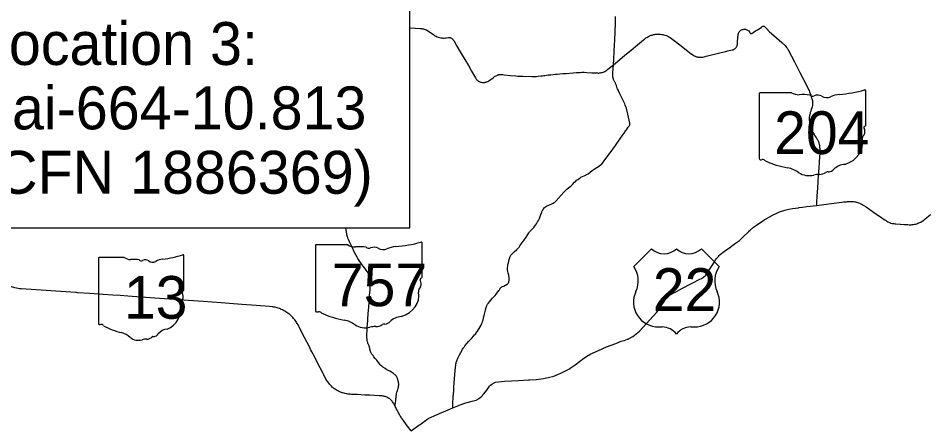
# Model space of a CAD drawing. Extents: x 1761803 to 2441803, y 509895 to 949895.
# Drawn here: x 1999264 to 2058370, y 753523 to 780187 of the extents above; entities that cross this region are included whole.
import ezdxf

# ---------------------------------------------------------------- set-up
doc = ezdxf.new("R2010")
doc.units = 0
for name, color, linetype in [('Default', 7, 'Continuous'), ('GM_X_County_Road_Text', 7, 'Continuous'), ('GM_X_Minor_Lake', 7, 'Continuous'), ('GM_X_Minor_River_Text', 7, 'Continuous'), ('GM_X_State_Location', 7, 'Continuous'), ('GM_X_Township_Road', 7, 'Continuous')]:
    doc.layers.add(name, color=color, linetype=linetype)

msp = doc.modelspace()

# ---------------------------------------------------------------- linework, layer by layer
at = {"layer": 'Default'}
msp.add_lwpolyline([(1995413, 766506), (2024789, 766506), (2024789, 781340), (1995413, 781340)], close=True, dxfattribs=at)
at = {"layer": 'GM_X_County_Road_Text'}
for p, q in [((2040554, 765146), (2039394, 763986)), ((2044963, 763986), (2043803, 765146)), ((2041018, 760041), (2041250, 760041)), ((2043107, 760041), (2043339, 760041))]:
    msp.add_line(p, q, dxfattribs=at)
for centre, radius, start, end in [((2041366, 765975), 1160, 225.573, 314.427), ((2042991, 765975), 1160, 225.573, 314.427), ((2038064, 763054), 1624, 334.54712, 35.00093), ((2046293, 763054), 1624, 144.99907, 205.45288), ((2041000, 761665), 1624, 154.83192, 270.63826), ((2043357, 761665), 1624, 269.36174, 25.16808), ((2041250, 758881), 1160, 36.8699, 90), ((2043107, 758881), 1160, 90, 143.1301)]:
    msp.add_arc(centre, radius, start, end, dxfattribs=at)
at = {"layer": 'GM_X_Minor_Lake'}
for points in [[(2038068, 777149), (2038085, 777516), (2038113, 777993), (2038138, 778487), (2038152, 778703), (2038183, 779333), (2038202, 779829), (2038213, 780293)], [(2045835, 778118), (2045864, 778126), (2045893, 778137), (2045932, 778154), (2045968, 778175), (2045999, 778199), (2046030, 778225), (2046063, 778262), (2046095, 778307), (2046116, 778353), (2046129, 778384), (2046138, 778421), (2046149, 778480), (2046157, 778584), (2046188, 778991), (2046194, 779050), (2046200, 779092), (2046207, 779130), (2046215, 779164), (2046225, 779197), (2046245, 779243), (2046267, 779283), (2046293, 779317), (2046320, 779348), (2046358, 779383), (2046381, 779401), (2046410, 779417), (2046453, 779438), (2046503, 779455), (2046559, 779465), (2046617, 779467), (2046671, 779461), (2046723, 779449), (2046772, 779431), (2046818, 779407), (2046857, 779380), (2046890, 779348), (2046929, 779300), (2046962, 779248), (2046986, 779212), (2046999, 779195), (2047013, 779184), (2047025, 779178), (2047041, 779173), (2047055, 779172), (2047068, 779175), (2047092, 779186), (2047188, 779249), (2047327, 779348), (2047457, 779433), (2047627, 779541), (2047718, 779600), (2047772, 779641), (2047798, 779659), (2047806, 779663), (2047816, 779667), (2047829, 779670), (2047842, 779671), (2047856, 779670), (2047869, 779668), (2047879, 779663), (2047888, 779658), (2047912, 779640), (2047957, 779603), (2048026, 779542), (2048071, 779482), (2048125, 779418)], [(2024789, 779552), (2024814, 779551), (2025158, 779531), (2025478, 779509), (2025571, 779500), (2025633, 779493), (2025678, 779486), (2025741, 779472), (2025801, 779453), (2025853, 779431), (2025908, 779402), (2026024, 779328), (2026227, 779185), (2026330, 779115), (2026377, 779081), (2026439, 779041), (2026512, 779000), (2026573, 778972), (2026645, 778944), (2026741, 778920), (2026814, 778903), (2026885, 778890), (2026948, 778882), (2026988, 778882), (2027045, 778885), (2027128, 778895), (2027185, 778902), (2027316, 778918), (2027339, 778920), (2027366, 778921), (2027393, 778920), (2027420, 778915), (2027445, 778906), (2027479, 778893), (2027508, 778877), (2027544, 778855), (2027572, 778831), (2027602, 778802), (2027622, 778779), (2027638, 778756), (2027657, 778722), (2027869, 778355), (2028081, 777996), (2028385, 777482), (2028616, 777087), (2028827, 776724), (2029079, 776288), (2029099, 776255), (2029125, 776219), (2029145, 776191), (2029161, 776172), (2029185, 776150), (2029215, 776124), (2029244, 776102), (2029279, 776079), (2029323, 776053), (2029365, 776033), (2029407, 776015), (2029455, 776003), (2029508, 775991), (2029555, 775985), (2029621, 775985), (2029672, 775992), (2029707, 775999), (2029743, 776007), (2029783, 776020), (2029826, 776037), (2029876, 776061), (2029938, 776097), (2030225, 776302), (2030317, 776368), (2030368, 776401), (2030416, 776428), (2030463, 776450), (2030502, 776466), (2030543, 776481), (2030580, 776492), (2030608, 776499), (2030641, 776504), (2030685, 776510), (2030746, 776512), (2030797, 776510), (2030849, 776506), (2030950, 776498), (2031368, 776452), (2031712, 776417), (2031833, 776405), (2031888, 776401), (2032002, 776395), (2032186, 776392), (2032744, 776387), (2033053, 776388), (2033173, 776395), (2033326, 776417)], [(2036084, 776653), (2036166, 776651), (2036338, 776646), (2036654, 776628), (2036891, 776613), (2037021, 776607), (2037071, 776604), (2037120, 776606), (2037170, 776610), (2037224, 776616), (2037281, 776629), (2037341, 776645), (2037409, 776668), (2037460, 776690), (2037510, 776715), (2037579, 776757), (2037638, 776800), (2037696, 776846), (2038068, 777149), (2038480, 777486), (2038820, 777769), (2039225, 778107), (2039631, 778442), (2040024, 778768), (2040090, 778820), (2040139, 778856), (2040191, 778894), (2040250, 778932), (2040306, 778964), (2040361, 778991), (2040429, 779023), (2040530, 779065), (2040594, 779085), (2040639, 779098), (2040689, 779110), (2040746, 779121), (2040800, 779130), (2040844, 779136), (2040902, 779140), (2040969, 779142), (2041047, 779141), (2041134, 779137), (2041214, 779128), (2041280, 779117), (2041359, 779099), (2041447, 779072), (2041522, 779047), (2041609, 779008), (2041682, 778969), (2041728, 778944), (2041770, 778916), (2042017, 778737), (2042396, 778441), (2042927, 778027), (2043166, 777846), (2043171, 777840), (2043241, 777787), (2043284, 777758), (2043326, 777732), (2043359, 777716), (2043398, 777698), (2043449, 777679), (2043490, 777666), (2043546, 777653), (2043596, 777644), (2043659, 777638), (2043717, 777635), (2043788, 777635), (2043849, 777640), (2043897, 777648), (2043979, 777667), (2044105, 777699), (2044372, 777769), (2044926, 777902), (2045376, 778007), (2045614, 778065), (2045732, 778093), (2045807, 778111), (2045835, 778118)], [(2048125, 779418), (2048136, 779404), (2048184, 779355), (2048253, 779292), (2048364, 779193), (2048703, 778894), (2049042, 778605), (2049103, 778550), (2049143, 778514), (2049182, 778477), (2049219, 778440), (2049262, 778395), (2049316, 778333), (2049357, 778280), (2049392, 778232), (2049424, 778184), (2049453, 778135), (2049489, 778073), (2049677, 777706), (2049873, 777325), (2050064, 776944), (2050225, 776635), (2050463, 776177), (2050671, 775777), (2050793, 775537), (2050827, 775460), (2050853, 775388), (2050928, 775155), (2050959, 775056), (2051016, 774888), (2051035, 774823), (2051045, 774776), (2051054, 774720), (2051055, 774652), (2051048, 774572), (2051035, 774479), (2051019, 774398), (2051005, 774334), (2050964, 774216), (2050927, 774113), (2050903, 774039), (2050890, 773983), (2050870, 773896), (2050855, 773830), (2050844, 773772), (2050836, 773720), (2050830, 773668), (2050828, 773619), (2050830, 773578), (2050835, 773531), (2050841, 773488), (2050855, 773415), (2050916, 773190), (2050967, 773012), (2050999, 772914), (2051032, 772825), (2051068, 772734), (2051103, 772662), (2051147, 772588), (2051196, 772517), (2051279, 772404), (2051306, 772364), (2051337, 772320), (2051357, 772287), (2051375, 772256), (2051395, 772219), (2051416, 772173), (2051421, 772162)], [(2027607, 754767), (2027608, 754967), (2027610, 755171), (2027614, 755350), (2027622, 755490), (2027637, 755669), (2027656, 755880), (2027667, 756106), (2027717, 756685), (2027756, 757181), (2027775, 757409), (2027793, 757558), (2027800, 757609), (2027809, 757678), (2027816, 757712), (2027822, 757739), (2027836, 757781), (2027855, 757831), (2027936, 758006), (2028044, 758220), (2028123, 758378), (2028200, 758527), (2028239, 758593), (2028281, 758660), (2028329, 758731), (2028387, 758806), (2028542, 758992), (2028628, 759093), (2028840, 759320), (2028945, 759431), (2029019, 759517), (2029072, 759577), (2029150, 759673), (2029211, 759759), (2029279, 759867), (2029324, 759939), (2029388, 760055), (2029446, 760165), (2029476, 760229), (2029508, 760302), (2029541, 760394), (2029567, 760486), (2029599, 760634), (2029662, 760884), (2029730, 761140), (2029760, 761249), (2029793, 761367), (2029815, 761423), (2029827, 761451), (2029842, 761480), (2029869, 761524), (2029910, 761580), (2030007, 761701), (2030063, 761767), (2030186, 761910), (2030355, 762094), (2030498, 762267), (2030603, 762414), (2030632, 762464), (2030653, 762501), (2030673, 762536), (2030691, 762559), (2030716, 762592), (2030738, 762616), (2030763, 762637), (2030800, 762659), (2030840, 762678), (2030925, 762712), (2030988, 762738), (2031031, 762758), (2031067, 762777), (2031107, 762801), (2031138, 762823), (2031160, 762842), (2031192, 762875), (2031211, 762901), (2031225, 762924), (2031241, 762959), (2031252, 763004), (2031264, 763068), (2031269, 763130), (2031272, 763180), (2031272, 763232), (2031271, 763263), (2031267, 763299), (2031261, 763340), (2031247, 763410), (2031214, 763543), (2031181, 763676), (2031173, 763718), (2031168, 763752), (2031163, 763793), (2031161, 763836), (2031166, 763901), (2031182, 764029), (2031196, 764118), (2031206, 764167), (2031220, 764230), (2031246, 764326), (2031277, 764441), (2031308, 764554), (2031320, 764601), (2031330, 764632), (2031358, 764684), (2031381, 764724), (2031407, 764756), (2031440, 764795), (2031480, 764836), (2031602, 764949), (2031762, 765090), (2031803, 765125), (2031835, 765155), (2031871, 765192), (2031920, 765251), (2031978, 765332), (2032083, 765480), (2032193, 765632), (2032229, 765685), (2032372, 765904), (2032484, 766075), (2032548, 766175), (2032564, 766199), (2032573, 766211), (2032608, 766251), (2032788, 766433), (2032881, 766537), (2032930, 766596), (2033044, 766763), (2033128, 766899), (2033176, 766980), (2033246, 767120), (2033297, 767243), (2033344, 767381), (2033395, 767532), (2033430, 767617), (2033457, 767668), (2033492, 767726), (2033528, 767772), (2033577, 767828), (2033617, 767861), (2033647, 767881), (2033715, 767917), (2033755, 767937), (2034060, 768074), (2034146, 768113), (2034211, 768149), (2034244, 768173), (2034297, 768217), (2034325, 768247), (2034846, 768833), (2034986, 768982), (2035057, 769046), (2035313, 769255), (2035401, 769338), (2035540, 769483), (2035615, 769556), (2035672, 769606), (2035749, 769668), (2035826, 769728), (2035900, 769779), (2035946, 769807), (2035989, 769827), (2036061, 769858), (2036169, 769903), (2036255, 769943), (2036369, 770009), (2036418, 770040), (2036683, 770246), (2036752, 770293), (2036815, 770334), (2036990, 770444), (2037158, 770555), (2037199, 770584), (2037261, 770631), (2037302, 770667), (2037355, 770729), (2037515, 770943), (2037851, 771410), (2038193, 771887), (2038536, 772359), (2038806, 772744), (2038881, 772851), (2038918, 772906), (2039038, 773072), (2039075, 773121), (2039096, 773151), (2039116, 773190), (2039130, 773225), (2039138, 773261), (2039140, 773304), (2039138, 773350), (2039126, 773427), (2039102, 773532), (2039011, 773930), (2038943, 774206), (2038915, 774314), (2038884, 774405), (2038842, 774515), (2038802, 774606), (2038771, 774673), (2038699, 774816), (2038490, 775244), (2038399, 775434), (2038367, 775503), (2038335, 775578), (2038300, 775670), (2038259, 775786), (2038228, 775886), (2038214, 775921), (2038196, 775957), (2038164, 776015), (2038125, 776086), (2038098, 776139), (2038079, 776182), (2038066, 776217), (2038054, 776258), (2038046, 776298), (2038039, 776350), (2038033, 776444), (2038032, 776534), (2038038, 776640), (2038068, 777149)], [(2033326, 776417), (2033377, 776424), (2033439, 776432), (2033522, 776444), (2033594, 776452), (2033697, 776465), (2033821, 776481), (2033985, 776497), (2034135, 776511), (2034269, 776523), (2034401, 776533), (2034582, 776548), (2034772, 776564), (2034985, 776580), (2035454, 776616), (2035671, 776635), (2035749, 776642), (2035819, 776646), (2035904, 776650), (2036014, 776654), (2036084, 776653)], [(2051421, 772162), (2051429, 772143), (2051443, 772108), (2051454, 772070), (2051466, 772030), (2051475, 771991), (2051483, 771945), (2051493, 771879), (2051510, 771742), (2051517, 771678), (2051521, 771627), (2051524, 771520), (2051523, 771433)], [(2051523, 771433), (2051519, 771364), (2051508, 771160), (2051485, 770798), (2051458, 770406), (2051423, 769925), (2051402, 769538), (2051371, 769090), (2051338, 768586), (2051307, 768161), (2051296, 767969)], [(2023890, 755325), (2023894, 755364), (2023901, 755441), (2023913, 755546), (2023922, 755618), (2023938, 755709), (2023955, 755785), (2023969, 755834), (2023989, 755893), (2024021, 755989), (2024033, 756026), (2024043, 756060), (2024051, 756097), (2024059, 756147), (2024066, 756185), (2024070, 756234), (2024071, 756275), (2024070, 756323), (2024064, 756373), (2024058, 756417), (2024048, 756464), (2024035, 756524), (2024021, 756580), (2024005, 756641), (2023992, 756687), (2023980, 756724), (2023968, 756753), (2023952, 756781), (2023936, 756807), (2023922, 756826), (2023897, 756854), (2023837, 756914), (2023803, 756945), (2023772, 756970), (2023737, 756997), (2023677, 757038), (2023606, 757084), (2023483, 757150), (2023401, 757195), (2023347, 757226), (2023304, 757254), (2023196, 757321), (2023143, 757355), (2023092, 757388), (2023040, 757424), (2022978, 757474), (2022914, 757532), (2022868, 757580), (2022827, 757630), (2022777, 757692), (2022743, 757738), (2022686, 757812), (2022642, 757868), (2022620, 757896), (2022546, 757988), (2022458, 758100), (2022400, 758173), (2022358, 758225), (2022330, 758263), (2022303, 758305), (2022274, 758353), (2022247, 758399), (2022227, 758450), (2022212, 758498), (2022201, 758550), (2022193, 758596), (2022185, 758651), (2022176, 758693), (2022167, 758734), (2022157, 758768), (2022139, 758819), (2022101, 758901), (2022087, 758932), (2022070, 758972), (2022053, 759017), (2022037, 759071), (2022020, 759153), (2022012, 759207), (2022005, 759270), (2022002, 759301), (2021999, 759345), (2021996, 759398), (2021996, 759517), (2021997, 759574), (2022007, 759778), (2022016, 759966), (2022024, 760072), (2022030, 760152), (2022090, 760928), (2022114, 761326), (2022137, 761665), (2022169, 762001), (2022178, 762101), (2022193, 762284), (2022205, 762449), (2022217, 762717), (2022225, 762853), (2022233, 762940), (2022237, 763003), (2022235, 763083), (2022226, 763168), (2022220, 763211), (2022209, 763267), (2022192, 763329), (2022168, 763396), (2022151, 763434), (2022137, 763462), (2022124, 763489), (2022112, 763511), (2022099, 763531), (2022085, 763555), (2022067, 763582), (2022051, 763606), (2022037, 763626), (2022016, 763655), (2021953, 763738), (2021853, 763871), (2021733, 764030), (2021602, 764219), (2021498, 764372), (2021414, 764502), (2021364, 764584), (2021282, 764737), (2021199, 764900), (2021121, 765055), (2021011, 765280), (2020927, 765454), (2020902, 765508), (2020865, 765590), (2020799, 765751), (2020779, 765798), (2020762, 765840), (2020750, 765873), (2020732, 765920), (2020722, 765951), (2020710, 765994), (2020700, 766042), (2020686, 766115), (2020644, 766363), (2020616, 766507)], [(2003124, 762276), (2003071, 762279), (2003018, 762283), (1999464, 762526), (1999355, 762535), (1999258, 762549), (1999157, 762566), (1999050, 762592), (1998984, 762611), (1998911, 762634), (1998834, 762663), (1998740, 762704), (1998645, 762752), (1998570, 762794), (1998475, 762856), (1998404, 762906), (1998365, 762935), (1998301, 762988), (1998241, 763040)], [(2004806, 762165), (2004790, 762166), (2003934, 762223), (2003124, 762276)], [(2020388, 755748), (2020335, 755767), (2020221, 755816), (2020142, 755853), (2020093, 755879), (2020025, 755916), (2019953, 755962), (2019831, 756049), (2019781, 756089), (2019739, 756124), (2019686, 756174), (2019640, 756218), (2019580, 756281), (2019510, 756366), (2019447, 756451), (2019374, 756560), (2019284, 756715), (2019186, 756909), (2019138, 757002), (2018759, 757746), (2018598, 758061), (2018413, 758422), (2018354, 758537), (2018250, 758739), (2018107, 759018), (2017764, 759690), (2017586, 760039), (2017509, 760184), (2017455, 760276), (2017416, 760338), (2017380, 760392), (2017302, 760499), (2017263, 760551), (2017217, 760602), (2017176, 760647), (2017122, 760703), (2017073, 760751), (2017023, 760799), (2016945, 760865), (2016905, 760898), (2016855, 760936), (2016789, 760983), (2016710, 761033), (2016640, 761075), (2016559, 761122), (2016497, 761153), (2016418, 761189), (2016362, 761213), (2016292, 761240), (2016218, 761267), (2016147, 761289), (2016075, 761310), (2016012, 761325), (2015935, 761342), (2015877, 761352), (2015813, 761362), (2015643, 761382), (2014777, 761445), (2013852, 761512), (2012502, 761611), (2011319, 761698), (2010371, 761767), (2009446, 761835), (2008484, 761903), (2007290, 761989), (2006423, 762052), (2005905, 762087), (2005429, 762123), (2004806, 762165)], [(2020819, 755656), (2020761, 755663), (2020685, 755674), (2020591, 755692), (2020506, 755713), (2020399, 755745), (2020388, 755748)], [(2023303, 755455), (2023252, 755477), (2023191, 755499), (2023149, 755512), (2023097, 755524), (2023035, 755534), (2022966, 755542), (2022885, 755548), (2022805, 755552), (2022490, 755567), (2022199, 755581), (2021863, 755598), (2021371, 755624), (2020984, 755643), (2020908, 755648), (2020840, 755653), (2020819, 755656)], [(2023807, 754933), (2023777, 754994), (2023747, 755048), (2023716, 755100), (2023677, 755156), (2023649, 755194), (2023614, 755232), (2023584, 755264), (2023531, 755312), (2023491, 755342), (2023453, 755371), (2023412, 755396), (2023359, 755427), (2023306, 755454), (2023303, 755455)], [(2024233, 754150), (2024184, 754223), (2024153, 754273), (2024126, 754318), (2024099, 754366), (2024074, 754415), (2024036, 754490), (2023966, 754623), (2023934, 754687), (2023885, 754782), (2023848, 754858), (2023821, 754908), (2023807, 754933)], [(2023821, 754908), (2023843, 754984), (2023863, 755074), (2023871, 755130), (2023880, 755215), (2023890, 755325)], [(2024577, 753666), (2024387, 753929), (2024262, 754107), (2024233, 754150)], [(2024874, 753257), (2024640, 753578), (2024577, 753666)]]:
    msp.add_lwpolyline(points, dxfattribs=at)
at = {"layer": 'GM_X_Minor_River_Text'}
for points in [[(2046903, 766281), (2046985, 766364), (2047207, 766540), (2047392, 766678), (2047876, 767004), (2048435, 767326), (2048683, 767444), (2048902, 767547), (2049243, 767662), (2049497, 767726), (2049737, 767771), (2050131, 767822), (2050181, 767828)], [(2050181, 767828), (2050393, 767856), (2050677, 767889), (2051296, 767969)], [(2051296, 767969), (2052101, 768068), (2052968, 768177), (2053082, 768193), (2053163, 768203), (2053252, 768212), (2053332, 768221), (2053384, 768226), (2053436, 768227), (2053494, 768229), (2053562, 768227), (2053635, 768224), (2053714, 768214), (2053795, 768202), (2053840, 768193), (2053910, 768178), (2053937, 768171), (2053998, 768152), (2054050, 768133), (2054112, 768108), (2054193, 768071), (2054232, 768053), (2054280, 768029), (2054340, 767995), (2054392, 767962), (2054535, 767869), (2055015, 767537), (2055571, 767160), (2055656, 767101), (2055759, 767034), (2055841, 766977), (2055898, 766941), (2055963, 766903), (2056016, 766873), (2056084, 766844), (2056152, 766819), (2056234, 766796), (2056280, 766789), (2056347, 766779), (2056404, 766773), (2056473, 766767), (2056757, 766748), (2056787, 766746)], [(2056787, 766746), (2057038, 766730), (2057167, 766722), (2057261, 766717), (2057347, 766712), (2057402, 766711), (2057472, 766712), (2057534, 766716), (2057615, 766726), (2057693, 766738), (2057766, 766755), (2057839, 766775), (2057915, 766801), (2057974, 766824), (2058044, 766856), (2058107, 766887), (2058193, 766942), (2058292, 767011), (2058390, 767089), (2058723, 767365), (2058739, 767379)], [(2045768, 765309), (2046031, 765499), (2046280, 765689), (2046579, 765966), (2046820, 766196), (2046891, 766268), (2046903, 766281)], [(2043804, 763207), (2043945, 763291), (2044096, 763425), (2044457, 763988), (2044634, 764250), (2044721, 764417), (2044789, 764507), (2044801, 764523), (2044914, 764647), (2044960, 764697), (2045016, 764759), (2045309, 764977), (2045724, 765278), (2045748, 765295), (2045766, 765308), (2045768, 765309)], [(2039029, 759248), (2039060, 759259), (2039341, 759415), (2039763, 759758), (2040905, 761000), (2041374, 761712), (2041492, 761871), (2041635, 762050), (2041723, 762108), (2042453, 762511), (2042478, 762524), (2043205, 762887), (2043706, 763149), (2043803, 763207), (2043804, 763207)], [(2036462, 758207), (2036556, 758264), (2037097, 758496), (2037622, 758743), (2038217, 758963), (2038565, 759116), (2038760, 759155), (2038989, 759234), (2039029, 759248)], [(2035246, 757343), (2035574, 757572), (2036131, 758009), (2036433, 758190), (2036462, 758207)], [(2032613, 756589), (2033036, 756615), (2033511, 756681), (2033817, 756743), (2034186, 756837), (2034643, 757023), (2035172, 757292), (2035224, 757328), (2035246, 757343)], [(2030065, 756241), (2030135, 756299), (2030289, 756403), (2030384, 756441), (2030961, 756511), (2031882, 756549), (2032537, 756585), (2032596, 756588), (2032613, 756589)], [(2027875, 754880), (2028005, 754937), (2028452, 755092), (2028863, 755198), (2029119, 755275), (2029274, 755363), (2029288, 755373), (2029438, 755479), (2029614, 755687), (2029813, 755924), (2029983, 756173), (2030061, 756237), (2030065, 756241)], [(2027607, 754767), (2027827, 754859), (2027875, 754880)], [(2026038, 754086), (2026073, 754106), (2026140, 754137), (2026431, 754259), (2027607, 754767)], [(2024874, 753257), (2025388, 753626)], [(2025388, 753626), (2025466, 753682), (2025818, 753932)], [(2025818, 753932), (2025906, 754000), (2025942, 754027), (2025964, 754042), (2025986, 754056), (2026010, 754072), (2026038, 754086)]]:
    msp.add_lwpolyline(points, dxfattribs=at)
at = {"layer": 'GM_X_Township_Road'}
for p, q in [((2047566, 775250), (2047566, 771023)), ((2049673, 775323), (2047635, 775323)), ((2054527, 773217), (2054527, 775427)), ((2054526, 773217), (2054527, 773217)), ((2025602, 763290), (2025602, 765501)), ((2018641, 765324), (2018641, 761097)), ((2020748, 765397), (2018710, 765397)), ((2004500, 764506), (2004500, 760280)), ((2006186, 764579), (2004555, 764579)), ((2010069, 762473), (2010069, 764684)), ((2025601, 763291), (2025602, 763290)), ((2010068, 762473), (2010069, 762473))]:
    msp.add_line(p, q, dxfattribs=at)
for centre, radius, start, end in [((2004564, 764515), 64.5, 98.1301, 188.1301), ((2006574, 765070), 626, 231.61951, 271.11188), ((2006782, 762206), 2246, 80.48669, 94.98827), ((2007292, 764537), 181, 219.79206, 297.10237), ((2007557, 764049), 375, 54.46668, 119.14113), ((2008041, 764719), 452, 233.85621, 294.82819), ((2008839, 763288), 1188, 97.34618, 120.76885), ((2008085, 770341), 5905, 275.84447, 288.90645), ((2010007, 764693), 62, 351.86209, 97.738), ((2010003, 762464), 66.3, 289.60381, 7.73413), ((2010055, 762310), 95.9, 107.94398, 210.33697), ((2009444, 762031), 576, 340.03296, 23.64957), ((2008416, 761266), 1477, 292.30889, 8.98584), ((2010291, 761547), 419, 136.8065, 186.92959), ((2004565, 760270), 65.1, 171.95839, 258.30661), ((2004575, 760703), 497, 267.33899, 280.60386), ((2004676, 760036), 179, 29.74838, 93.27175), ((2006937, 763833), 4265, 240.41292, 257.1985), ((2005666, 758381), 1334, 47.18416, 75.83597), ((2008014, 759870), 477, 282.87319, 323.27711), ((2009039, 759093), 809, 94.40312, 142.57675), ((2007109, 760015), 847, 230.70037, 286.29184), ((2007598, 758554), 696, 85.69512, 111.20995), ((2007660, 759698), 451, 268.77702, 315.54927), ((2008068, 759289), 127, 65.75173, 132.64842)]:
    msp.add_arc(centre, radius, start, end, dxfattribs=at)
for centre, major_axis, start_param, end_param in [((2052048, 781085), (7382, 0), 4.814394, 5.042369), ((2054450, 775437), (77.5, 0), 6.141152, 7.989035), ((2047646, 775259), (80.6, 0), 1.712693, 3.28349), ((2050159, 775813), (782, 0), 4.042523, 4.731795), ((2050418, 772950), (2808, 0), 1.404758, 1.657858), ((2051056, 775281), (226, 0), 3.836095, 5.185415), ((2051387, 774792), (469, 0), 0.950623, 2.079405), ((2051992, 775462), (564, 0), 4.081561, 5.145723), ((2052989, 774032), (1485, 0), 1.699011, 2.107814), ((2054509, 773054), (120, 0), 1.883978, 3.671073), ((2054444, 773208), (82.9, 0), 5.05454, 6.418171), ((2054805, 772291), (524, 0), 2.387724, 3.262537), ((2053746, 772775), (720, 0), 5.934695, 6.695948), ((2052461, 772010), (1846, 0), 5.101752, 6.440018), ((2047647, 771014), (81.4, 0), 3.00124, 4.508301), ((2047659, 771447), (621, 0), 4.665946, 4.897461), ((2047786, 770780), (224, 0), 0.519207, 1.627899), ((2050612, 774577), (5331, 0), 4.195997, 4.488961), ((2049023, 769125), (1668, 0), 0.823519, 1.323587), ((2052026, 770033), (159, 0), 1.147584, 2.315152), ((2051958, 770614), (597, 0), 4.937069, 5.64225), ((2053240, 769837), (1011, 0), 1.647645, 2.488434), ((2050827, 770759), (1058, 0), 4.026481, 4.996735), ((2051439, 769297), (870, 0), 1.495662, 1.94098), ((2051516, 770442), (564, 0), 4.691044, 5.507374), ((2023123, 771159), (7382, 0), 4.814394, 5.042369), ((2025525, 765510), (77.5, 0), 6.141152, 7.989035), ((2018721, 765333), (80.6, 0), 1.712693, 3.28349), ((2021234, 765887), (782, 0), 4.042523, 4.731795), ((2021493, 763024), (2808, 0), 1.404758, 1.657858), ((2022131, 765355), (226, 0), 3.836095, 5.185415), ((2022462, 764866), (469, 0), 0.950623, 2.079405), ((2023067, 765536), (564, 0), 4.081561, 5.145723), ((2024064, 764106), (1485, 0), 1.699011, 2.107814), ((2025584, 763128), (120, 0), 1.883978, 3.671073), ((2024821, 762849), (720, 0), 5.934695, 6.695948), ((2025519, 763282), (82.9, 0), 5.05454, 6.418171), ((2025880, 762365), (524, 0), 2.387724, 3.262537), ((2023536, 762084), (1846, 0), 5.101752, 6.440018), ((2018722, 761088), (81.4, 0), 3.00124, 4.508301), ((2018734, 761520), (621, 0), 4.665946, 4.897461), ((2018861, 760853), (224, 0), 0.519207, 1.627899), ((2021688, 764651), (5331, 0), 4.195997, 4.488961), ((2024315, 759911), (1011, 0), 1.647645, 2.488434), ((2020098, 759199), (1668, 0), 0.823519, 1.323587), ((2021902, 760832), (1058, 0), 4.026481, 4.996735), ((2022591, 760516), (564, 0), 4.691044, 5.507374), ((2023101, 760107), (159, 0), 1.147584, 2.315152), ((2023033, 760688), (597, 0), 4.937069, 5.64225), ((2022514, 759371), (870, 0), 1.495662, 1.94098)]:
    msp.add_ellipse(centre, major_axis=major_axis, ratio=0.8, start_param=start_param, end_param=end_param, dxfattribs=at)

# ---------------------------------------------------------------- texts
at = {"layer": 'GM_X_County_Road_Text'}
msp.add_text('22', height=2784.4, dxfattribs=at).set_placement((2040637, 761085))
at = {"layer": 'GM_X_State_Location'}
for s, p in [('Location 3:', (1996576, 777130)), ('Fai-664-10.813', (1996576, 772930)), ('(CFN 1886369)', (1996576, 768730))]:
    msp.add_text(s, height=2800, dxfattribs=at).set_placement(p)
at = {"layer": 'GM_X_Township_Road'}
for s, p in [('204', (2048545, 771322)), ('757', (2019713, 761395)), ('13', (2006158, 760578))]:
    msp.add_text(s, height=2784.4, dxfattribs=at).set_placement(p)

doc.saveas('drawing.dxf')
